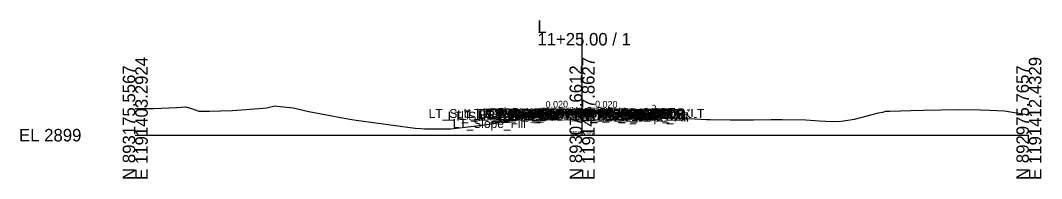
# Model space of a CAD drawing. Extents: x -26 to 203, y -10 to 7027.
# Drawn here: x -25.7 to 202.8, y 2490.3 to 2525.6 of the extents above; entities that cross this region are included whole.
import ezdxf

# ---------------------------------------------------------------- set-up
doc = ezdxf.new("R2010")
doc.units = 0
for name, color, linetype in [('Default', 7, 'Continuous'), ('Exist CMT Pavement', 7, 'Continuous'), ('Exist Cross Section Cell', 7, 'Continuous'), ('Exist XS Center Line Elevation Label', 7, 'Continuous'), ('Exist XS Ground Line', 7, 'Continuous'), ('Prop CMT Concrete Structures', 7, 'Continuous'), ('Prop CMT Pvmt Course 1', 7, 'Continuous'), ('Prop CMT Pvmt Course 2', 7, 'Continuous'), ('Prop CMT Pvmt Course 2 Wedge', 7, 'Continuous'), ('Prop CMT Pvmt Course 3', 7, 'Continuous'), ('Prop CMT Pvmt Course 3 Wedge', 7, 'Continuous'), ('Prop CMT Pvmt Surface', 7, 'Continuous'), ('Prop CMT Pvmt Surface Shoulder', 7, 'Continuous'), ('Prop CMT Pvmt Wedge Surface 3', 7, 'Continuous'), ('Prop CMT Shld Paved Course 1', 7, 'Continuous'), ('Prop CMT Shld Paved Course 2', 7, 'Continuous'), ('Prop CMT Shld Paved Course 3', 7, 'Continuous'), ('Prop CMT Slope Grass', 7, 'Continuous'), ('Prop CMT Subgrade Earthwork', 7, 'Continuous'), ('Scratch_Level_6', 7, 'Continuous')]:
    doc.layers.add(name, color=color, linetype=linetype)

msp = doc.modelspace()

# ---------------------------------------------------------------- linework, layer by layer
at = {"layer": 'Exist CMT Pavement'}
for points in [[(89, 2504.83), (86.79, 2504.79), (86.57, 2504.58)], [(89, 2504.63), (89, 2504.83)], [(100, 2504.95), (91.32, 2504.92)], [(91.32, 2504.92), (95.66, 2504.94)], [(95.66, 2504.94), (100, 2504.95)], [(104.54, 2504.81), (100, 2504.95)], [(100, 2504.95), (109.07, 2504.67)], [(109.07, 2504.67), (104.54, 2504.81)], [(111, 2504.83), (113.21, 2504.79), (113.43, 2504.58)], [(111, 2504.63), (111, 2504.83)], [(86.57, 2504.58), (89, 2504.63)], [(113.43, 2504.58), (111, 2504.63)]]:
    msp.add_lwpolyline(points, dxfattribs=at)
at = {"layer": 'Exist Cross Section Cell'}
for p, q in [((100, 2500), (100, 2522.84)), ((0, 2500), (100, 2500)), ((100, 2500), (200, 2500))]:
    msp.add_line(p, q, dxfattribs=at)
at = {"layer": 'Exist XS Center Line Elevation Label'}
for points in [[(100, 2505.05), (91.32, 2504.88)], [(100, 2505.05), (109.07, 2504.87)]]:
    msp.add_lwpolyline(points, dxfattribs=at)
at = {"layer": 'Exist XS Ground Line'}
for points in [[(100, 2505.14), (91.32, 2504.96)], [(100, 2505.14), (109.07, 2504.96)]]:
    msp.add_lwpolyline(points, dxfattribs=at)
at = {"layer": 'Prop CMT Concrete Structures'}
for points in [[(100, 2505.26), (89, 2505.04)], [(100, 2505.26), (111, 2505.04)]]:
    msp.add_lwpolyline(points, dxfattribs=at)
at = {"layer": 'Prop CMT Pvmt Course 1'}
for points in [[(100, 2505.26), (89, 2505.04)], [(89, 2505.04), (89, 2504.83)], [(89, 2504.83), (91.32, 2504.88)], [(91.32, 2504.88), (89, 2504.83)], [(89, 2504.83), (89, 2504.63)], [(91.32, 2504.96), (100, 2505.14)], [(91.32, 2504.88), (91.32, 2504.96)], [(91.32, 2504.67), (91.32, 2504.88)], [(100, 2505.05), (100, 2505.26)], [(100, 2505.26), (111, 2505.04)], [(100, 2505.05), (100, 2505.26)], [(100, 2505.14), (100, 2505.05), (100, 2505.05)], [(109.07, 2504.96), (100, 2505.14)], [(100, 2505.14), (100, 2505.05), (100, 2505.05)], [(109.07, 2504.87), (109.07, 2504.96)], [(111, 2504.83), (109.07, 2504.87)], [(109.07, 2504.66), (109.07, 2504.87)], [(109.07, 2504.87), (111, 2504.83)], [(111, 2505.04), (111, 2504.83)], [(111, 2504.83), (111, 2504.63)], [(89, 2504.63), (91.32, 2504.67)], [(111, 2504.63), (109.07, 2504.66)]]:
    msp.add_lwpolyline(points, dxfattribs=at)
at = {"layer": 'Prop CMT Pvmt Course 2'}
for points in [[(100, 2504.85), (91.32, 2504.67)], [(100, 2504.85), (109.07, 2504.66)]]:
    msp.add_lwpolyline(points, dxfattribs=at)
at = {"layer": 'Prop CMT Pvmt Course 3'}
for points in [[(91.32, 2504.67), (89, 2504.63)], [(89, 2504.63), (89, 2504.29)], [(89, 2504.29), (91.32, 2504.34)], [(91.32, 2504.34), (91.32, 2504.67)], [(109.07, 2504.66), (111, 2504.63)], [(109.07, 2504.33), (109.07, 2504.66)], [(111, 2504.29), (109.07, 2504.33)], [(111, 2504.63), (111, 2504.29)]]:
    msp.add_lwpolyline(points, dxfattribs=at)
at = {"layer": 'Prop CMT Pvmt Course 3 Wedge'}
for p, q in [((0, 2505.95), (1.86, 2505.94)), ((1.86, 2505.94), (4.08, 2505.98)), ((4.08, 2505.98), (9.23, 2506.17)), ((9.23, 2506.17), (11.33, 2506.33)), ((11.33, 2506.33), (12.63, 2505.94)), ((12.63, 2505.94), (14.21, 2505.37)), ((14.21, 2505.37), (16.63, 2505.34)), ((16.63, 2505.34), (19.1, 2505.42)), ((19.1, 2505.42), (21.74, 2505.49)), ((21.74, 2505.49), (25.76, 2505.82)), ((25.76, 2505.82), (26.65, 2505.89)), ((26.65, 2505.89), (27.71, 2505.97)), ((27.71, 2505.97), (29.43, 2506.08)), ((29.43, 2506.08), (31.25, 2506.53)), ((31.25, 2506.53), (31.72, 2506.51)), ((31.72, 2506.51), (35.33, 2506.1)), ((35.33, 2506.1), (38.88, 2505.29)), ((38.88, 2505.29), (46.73, 2503.77)), ((87.41, 2504.13), (90.99, 2504.85)), ((90.99, 2504.85), (91.32, 2504.92)), ((91.32, 2504.92), (99.55, 2504.96)), ((99.55, 2504.96), (100, 2504.95)), ((100, 2504.95), (109.07, 2504.67)), ((160.97, 2503.58), (166.31, 2505.01)), ((166.31, 2505.01), (167.33, 2505.17)), ((167.33, 2505.17), (168, 2505.33)), ((168, 2505.33), (168.86, 2505.38)), ((168.86, 2505.38), (173.62, 2505.53)), ((173.62, 2505.53), (176.4, 2505.59)), ((176.4, 2505.59), (184.33, 2505.74)), ((184.33, 2505.74), (189.16, 2505.66)), ((189.16, 2505.66), (191.24, 2505.59)), ((191.24, 2505.59), (194.53, 2505.47)), ((194.53, 2505.47), (200, 2504.54)), ((46.73, 2503.77), (48.47, 2503.5)), ((48.47, 2503.5), (49.43, 2503.36)), ((49.43, 2503.36), (62.68, 2501.58)), ((76.35, 2502.07), (81.98, 2502.8)), ((81.98, 2502.8), (83.11, 2502.99)), ((83.11, 2502.99), (87.41, 2504.13)), ((109.07, 2504.67), (109.76, 2504.59)), ((109.76, 2504.59), (113.84, 2504.18)), ((113.84, 2504.18), (114.23, 2504.15)), ((114.23, 2504.15), (119.93, 2503.85)), ((119.93, 2503.85), (125.2, 2503.65)), ((125.2, 2503.65), (127.82, 2503.47)), ((127.82, 2503.47), (128.68, 2503.47)), ((128.68, 2503.47), (133.13, 2503.41)), ((133.13, 2503.41), (136.19, 2503.43)), ((136.19, 2503.43), (138.38, 2503.45)), ((138.38, 2503.45), (142.32, 2503.5)), ((142.32, 2503.5), (143.13, 2503.48)), ((143.13, 2503.48), (144.79, 2503.51)), ((144.79, 2503.51), (150.11, 2503.43)), ((150.11, 2503.43), (153.07, 2503.17)), ((153.07, 2503.17), (155.94, 2503.05)), ((155.94, 2503.05), (157.96, 2503.16)), ((157.96, 2503.16), (160.97, 2503.58)), ((62.68, 2501.58), (63.95, 2501.46)), ((63.95, 2501.46), (64.74, 2501.45)), ((64.74, 2501.45), (69.93, 2501.45)), ((69.93, 2501.45), (70.65, 2501.45)), ((70.65, 2501.45), (76.35, 2502.07))]:
    msp.add_line(p, q, dxfattribs=at)
at = {"layer": 'Prop CMT Pvmt Surface'}
for points in [[(87, 2505), (85, 2504.84), (80.54, 2502.61)], [(113, 2505), (115, 2504.84), (116.63, 2504.03)]]:
    msp.add_lwpolyline(points, dxfattribs=at)
at = {"layer": 'Prop CMT Pvmt Surface Shoulder'}
for points in [[(89, 2505.04), (87, 2505)], [(111, 2505.04), (113, 2505)]]:
    msp.add_lwpolyline(points, dxfattribs=at)
at = {"layer": 'Prop CMT Shld Paved Course 1'}
for points in [[(89, 2505.04), (87, 2505), (86.79, 2504.79)], [(86.79, 2504.79), (89, 2504.83)], [(89, 2504.83), (89, 2505.04)], [(89, 2504.83), (89, 2505.04)], [(91.32, 2504.88), (89, 2504.83)], [(100, 2505.14), (91.32, 2504.96)], [(91.32, 2504.96), (91.32, 2504.88)], [(100, 2505.14), (109.07, 2504.96)], [(109.07, 2504.96), (109.07, 2504.87)], [(109.07, 2504.87), (111, 2504.83)], [(111, 2505.04), (113, 2505), (113.21, 2504.79)], [(111, 2504.83), (111, 2505.04)], [(111, 2504.83), (111, 2505.04)], [(113.21, 2504.79), (111, 2504.83)]]:
    msp.add_lwpolyline(points, dxfattribs=at)
at = {"layer": 'Prop CMT Shld Paved Course 2'}
for points in [[(100, 2505.05), (89, 2504.83)], [(89, 2504.83), (89, 2505.04)], [(100, 2505.05), (111, 2504.83)], [(111, 2504.83), (111, 2505.04)]]:
    msp.add_lwpolyline(points, dxfattribs=at)
at = {"layer": 'Prop CMT Shld Paved Course 3'}
for points in [[(89, 2504.63), (89, 2505.04)], [(100, 2504.85), (89, 2504.63)], [(100, 2504.85), (111, 2504.63)], [(111, 2504.63), (111, 2505.04)]]:
    msp.add_lwpolyline(points, dxfattribs=at)
at = {"layer": 'Prop CMT Slope Grass'}
for points in [[(89, 2504.63), (86.57, 2504.58), (86.07, 2504.57), (85.73, 2504.23)], [(85.73, 2504.23), (89, 2504.29)], [(89, 2504.29), (89, 2504.63)], [(111, 2504.63), (113.43, 2504.58), (113.93, 2504.57), (114.27, 2504.23)], [(111, 2504.29), (111, 2504.63)], [(114.27, 2504.23), (111, 2504.29)]]:
    msp.add_lwpolyline(points, dxfattribs=at)
at = {"layer": 'Prop CMT Subgrade Earthwork'}
for points in [[(85.73, 2504.23), (85.11, 2504.85)], [(91.32, 2504.34), (91.34, 2504.92)], [(114.27, 2504.23), (114.89, 2504.85)], [(89, 2504.29), (85.73, 2504.23)], [(91.32, 2504.34), (89, 2504.29)], [(109.07, 2504.33), (109.06, 2504.67)], [(109.07, 2504.33), (111, 2504.29)], [(111, 2504.29), (114.27, 2504.23)]]:
    msp.add_lwpolyline(points, dxfattribs=at)

# ---------------------------------------------------------------- texts
at = {"layer": 'Default'}
msp.add_text('-', height=0.0001, dxfattribs=at).set_placement((0, 2500))
at = {"layer": 'Exist Cross Section Cell'}
for s, p in [('L', (90, 2522.84)), ('11+25.00 / 1', (90, 2520.04)), ('EL 2899', (-26, 2498.6))]:
    msp.add_text(s, height=2.8, dxfattribs=at).set_placement(p)
for s, p in [('E 1191403.2924', (2.8, 2490)), ('E 1191407.8627', (102.8, 2490)), ('E 1191412.4329', (202.8, 2490)), ('N 893175.5567', (0, 2490)), ('N 893075.6612', (100, 2490)), ('N 892975.7657', (200, 2490))]:
    msp.add_text(s, height=2.8, rotation=90, dxfattribs=at).set_placement(p)
at = {"layer": 'Prop CMT Pvmt Course 2 Wedge'}
for s, p in [('LT_Sub_Trench_Out_DLT', (65.68, 2503.85)), ('LT_Sub_Trench_Out', (69.94, 2503.23)), ('LT_PS3_Shelf_Out', (72.06, 2503.57)), ('LT_GS_OS_CTL', (74.37, 2503.84)), ('LT_PV_Sub_Tie_Out', (76.28, 2503.92)), ('LT_PS3_OEOP', (76.81, 2503.58)), ('LT_PS2_OEOP', (77.02, 2503.79)), ('LT_PS1_OEOP', (77.8, 2504)), ('LT_PV_OEEOP_EG', (78.87, 2503.92)), ('LT_Sub_OEOT', (79.08, 2503.29)), ('LT_PV2_OEOT', (79.17, 2503.83)), ('LT_PV3_OEOT', (79.17, 2503.63)), ('LT_PV1_OEOT', (79.74, 2504.04)), ('LT_Sub_OEEOP', (80.54, 2503.34)), ('LT_PV2_OEEOP', (80.63, 2503.88)), ('LT_PV3_OEEOP', (80.63, 2503.67)), ('LT_PV1_OEEOP', (81.2, 2503.96)), ('LT_PV_EG_TestPt', (82.07, 2503.94)), ('RT_PV_IEEOP_EG', (88.14, 2503.95)), ('LT_PV_IEEOP_EG', (88.19, 2503.95)), ('RT_PV2_IEEOP', (89.91, 2504.05)), ('RT_PV3_IEEOP', (89.91, 2503.85)), ('LT_PV2_IEEOP', (89.95, 2504.05)), ('LT_PV3_IEEOP', (89.95, 2503.85)), ('RT_PV1_IEEOP', (90.47, 2504.14)), ('LT_PV1_IEEOP', (90.52, 2504.14)), ('RT_PV_EG_TestPt', (90.9, 2503.81)), ('PV2_PGL', (93.91, 2504.05)), ('RT_PV_Sub_Tie_Out', (93.96, 2503.67)), ('PV1_PGL', (94.47, 2504.26)), ('RT_Sub_Trench_Out_DLT', (95.41, 2503.85)), ('RT_PV_OEEOP_EG', (96.57, 2503.67)), ('RT_Sub_OEEOP', (98.24, 2503.33)), ('RT_PV2_OEEOP', (98.33, 2503.87)), ('RT_PV3_OEEOP', (98.33, 2503.66)), ('RT_Sub_Trench_Out', (98.42, 2503.23)), ('RT_PV1_OEEOP', (98.9, 2503.96)), ('RT_PS3_Shelf_Out', (99.86, 2503.57)), ('RT_Sub_OEOT', (101.03, 2503.29)), ('RT_PV2_OEOT', (101.13, 2503.83)), ('RT_PV3_OEOT', (101.13, 2503.63)), ('RT_PV1_OEOT', (101.69, 2504.04)), ('RT_PS2_OEOP', (103.4, 2503.79)), ('RT_PS3_OEOP', (103.61, 2503.58)), ('RT_PS1_OEOP', (103.76, 2504)), ('RT_GS_OS_CTL', (104.32, 2503.84)), ('RT_Slope_Fill', (107.1, 2503.03)), ('LT_Slope_Fill', (71.06, 2501.61))]:
    msp.add_text(s, height=2, dxfattribs=at).set_placement(p)
at = {"layer": 'Prop CMT Pvmt Surface Shoulder'}
for rotation, p in [(1.1458, (91.86, 2506.1)), (358.8542, (102.9, 2506.2))]:
    msp.add_text('0.020', height=1.5, rotation=rotation, dxfattribs=at).set_placement(p)
at = {"layer": 'Prop CMT Pvmt Wedge Surface 3'}
for rotation, p in [(26.5651, (81.37, 2503.87)), (333.4349, (115.09, 2505.64))]:
    msp.add_text('2:1', height=1.5, rotation=rotation, dxfattribs=at).set_placement(p)
at = {"layer": 'Scratch_Level_6'}
msp.add_text('2903.95', height=1, dxfattribs=at).set_placement((97.5, 2499.95))

doc.saveas('drawing.dxf')
